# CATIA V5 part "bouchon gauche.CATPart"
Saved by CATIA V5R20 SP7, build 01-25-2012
Part number: bouchon gauche
Bounding box of the stored display mesh (mm): x 8.61 to 22.615, y -79 to -65, z 49.211 to 62.853
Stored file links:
  F:\Travaux\Modélisations\CFAO_2011\CFAO_2011_MMS\CFAO_2011_MMS_DONE\CFAO_2011_MMS_jboiteux\Catia\bouchon gauche.CATPart
  U:\finthinkmotion\stepper.CATProduct
  F:\Travaux\Modélisations\CFAO_2011\CFAO_2011_MMS\CFAO_2011_MMS_DONE\CFAO_2011_MMS_jboiteux\Catia\rondelle2 pied gauche.CATPart
  F:\Travaux\Modélisations\CFAO_2011\CFAO_2011_MMS\CFAO_2011_MMS_DONE\CFAO_2011_MMS_jboiteux\Catia\bati.CATPart
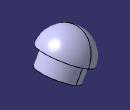
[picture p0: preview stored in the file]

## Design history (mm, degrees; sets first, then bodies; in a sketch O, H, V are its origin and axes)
Parameters
  rayontube = 9 mm {= External.royontubebati}
External parameters (linked from other documents)
  External.royontubebati = 9 mm
Set1
  DatumSurface1: linked copy from another document
  DatumCurve1: linked copy from another document
  DatumCurve2: linked copy from another document
  DatumSurface2: linked copy from another document
  DatumCurve3: linked copy from another document
  DatumCurve4: linked copy from another document
Body1 (main body)
  Sketch1 on face of DatumSurface1, origin (-20.2828, 0, 35.1308), H (0, 1, 0), V (0.866, 0, 0.5)
    projected circle E1 centre (-72, 41.4454) radius 5.5 from edge of DatumCurve1
    projected circle E2 centre (-72, 41.4454) radius 5 from edge of DatumCurve2
  Pad1: profile Sketch1, direction (0.5, 0, -0.866), length 4.5 {= rayontube /2}
  Sketch2 on face of DatumSurface2, origin (-20.2828, 0, 35.1308), H (0, 1, 0), V (0.866, 0, 0.5)
    projected circle E1 centre (-72, 41.4454) radius 7 from edge of DatumCurve3
  Pad2: profile Sketch2, direction (-0.5, 0, 0.866), length 7 {= rayontube *5/9+2mm}
  Fillet1: radius 7 {= rayontube *5/9+2mm}, on edge [end face of Pad2 | face of Pad2 from Sketch2.E1]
